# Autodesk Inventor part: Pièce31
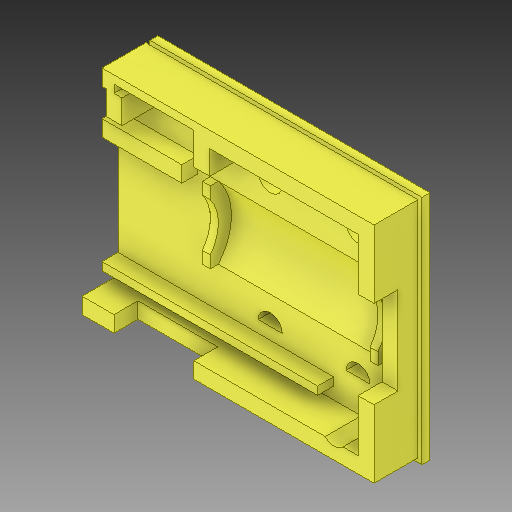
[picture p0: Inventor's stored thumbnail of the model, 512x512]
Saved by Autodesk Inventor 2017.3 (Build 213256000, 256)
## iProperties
Created: 2007-12
Part Number: Pièce31
Material: Générique
Document SubType Name: Modeling
Designer: ficho
Density: 1 g/cm^3
Appearance: Par défaut
Author: ficho
Sending System: SolidWorks 2009
Last Author: christophe
Last Saved: 2011-02-10
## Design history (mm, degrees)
feature "Enlèv. mat.-Extru.12"
node "Solide1"
